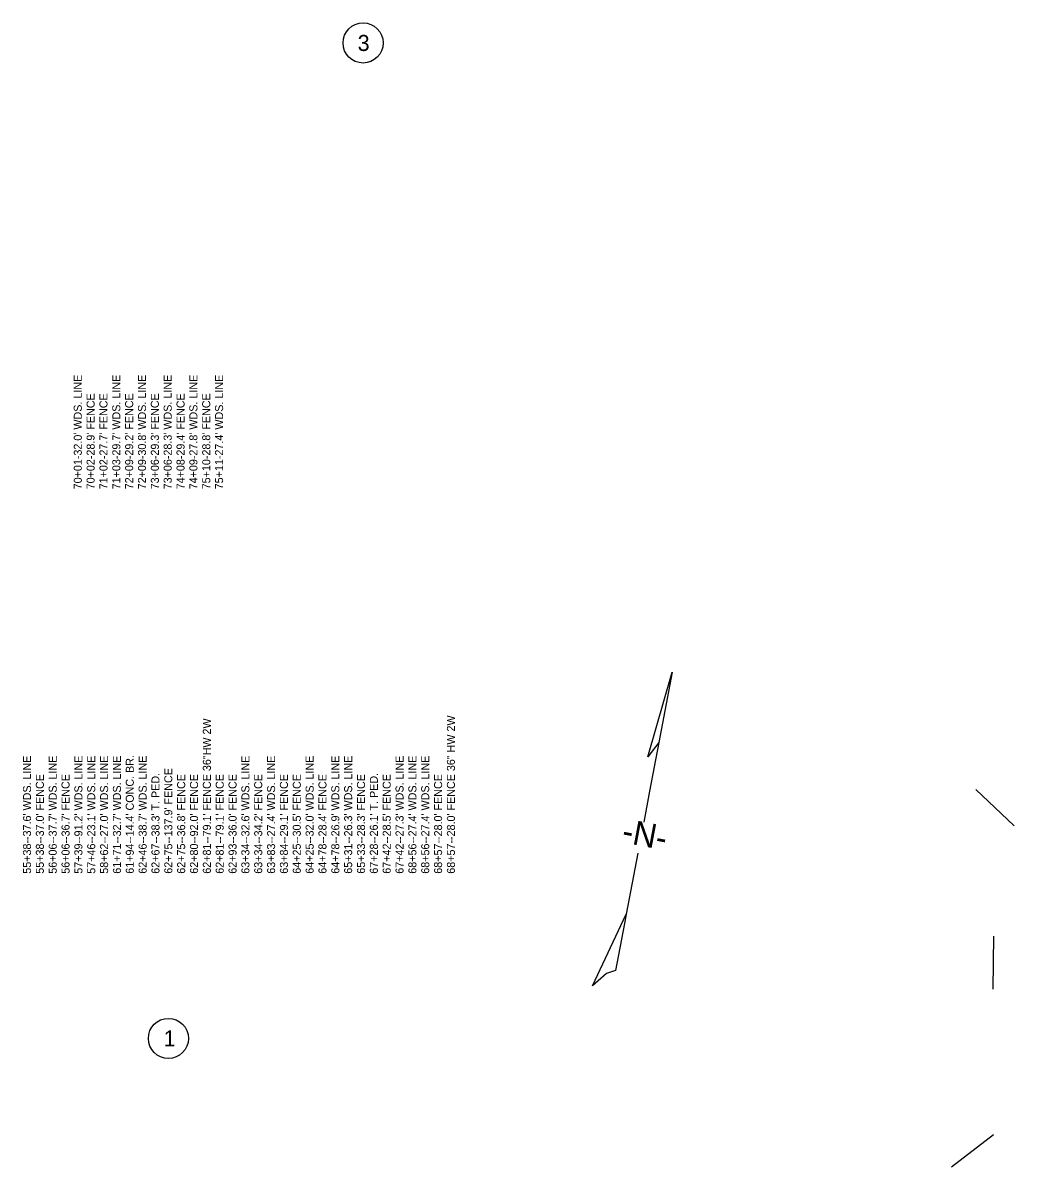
# Model space of a CAD drawing. Extents: x 1964853 to 1967410, y 1117103 to 1120421.
# Drawn here: x 1966020 to 1966637, y 1118961 to 1119674 of the extents above; entities that cross this region are included whole.
import ezdxf

# ---------------------------------------------------------------- set-up
doc = ezdxf.new("R2010")
doc.units = 0
for name, color, linetype in [('Level 10', 7, 'Continuous'), ('Level 12', 7, 'Continuous'), ('Level 2', 7, 'Continuous'), ('Level 24', 7, 'Continuous')]:
    doc.layers.add(name, color=color, linetype=linetype)

msp = doc.modelspace()

# ---------------------------------------------------------------- linework, layer by layer
at = {"layer": 'Level 10'}
for p, q in [((1966613.5, 1119196.31), (1966637.41, 1119173.56)), ((1966624.49, 1119104.85), (1966624.19, 1119071.85)), ((1966624.49, 1118981.29), (1966598.39, 1118961.09))]:
    msp.add_line(p, q, dxfattribs=at)
at = {"layer": 'Level 12'}
for centre in [(1966231.96, 1119661.16), (1966110.74, 1119041.23)]:
    msp.add_circle(centre, 12.5, dxfattribs=at)
at = {"layer": 'Level 2'}
for p, q in [((1966409.3, 1119216.53), (1966424.36, 1119269.24)), ((1966424.36, 1119269.24), (1966416.1, 1119225.56)), ((1966416.1, 1119225.56), (1966409.3, 1119216.53)), ((1966416.1, 1119225.56), (1966410.37, 1119195.28)), ((1966410.37, 1119195.28), (1966406.72, 1119175.97)), ((1966403.07, 1119156.7), (1966395.85, 1119118.53)), ((1966374.84, 1119074.05), (1966395.85, 1119118.53)), ((1966395.85, 1119118.53), (1966394.76, 1119112.75)), ((1966394.76, 1119112.75), (1966389.22, 1119083.49))]:
    msp.add_line(p, q, dxfattribs=at)
msp.add_lwpolyline([(1966389.22, 1119083.49), (1966383.46, 1119081.62), (1966374.84, 1119074.05)], dxfattribs=at)

# ---------------------------------------------------------------- texts
at = {"layer": 'Level 12'}
for s, p in [('3', (1966228.59, 1119656.16)), ('1', (1966107.7, 1119036.23))]:
    msp.add_text(s, height=10, dxfattribs=at).set_placement(p)
at = {"layer": 'Level 2'}
msp.add_text('-N-', height=15, rotation=349.28859, dxfattribs=at).set_placement((1966392.47, 1119163.5))
at = {"layer": 'Level 24'}
for s, p in [("70+01-32.0' WDS. LINE", (1966056.78, 1119383.19)), ("71+03-29.7' WDS. LINE", (1966080.78, 1119383.19)), ("72+09-30.8' WDS. LINE", (1966096.78, 1119383.19)), ("73+06-28.3' WDS. LINE", (1966112.78, 1119383.19)), ("74+09-27.8' WDS. LINE", (1966128.78, 1119383.19)), ("75+11-27.4' WDS. LINE", (1966144.78, 1119383.19)), ("70+02-28.9' FENCE  ", (1966064.78, 1119383.19)), ("71+02-27.7' FENCE  ", (1966072.78, 1119383.19)), ("72+09-29.2' FENCE  ", (1966088.78, 1119383.19)), ("73+06-29.3' FENCE  ", (1966104.78, 1119383.19)), ("74+08-29.4' FENCE  ", (1966120.78, 1119383.19)), ("75+10-28.8' FENCE  ", (1966136.78, 1119383.19)), ('62+81--79.1\' FENCE 36"HW 2W ', (1966137.17, 1119143.8)), ('68+57--28.0\' FENCE 36" HW 2W ', (1966289.17, 1119143.8)), ("55+38--37.6' WDS. LINE", (1966025.17, 1119143.8)), ("56+06--37.7' WDS. LINE", (1966041.17, 1119143.8)), ("57+39--91.2' WDS. LINE", (1966057.17, 1119143.8)), ("57+46--23.1' WDS. LINE", (1966065.17, 1119143.8)), ("58+62--27.0' WDS. LINE", (1966073.17, 1119143.8)), ("61+71--32.7' WDS. LINE", (1966081.17, 1119143.8)), ("61+94--14.4' CONC. BR.  ", (1966089.17, 1119143.8)), ("62+46--38.7' WDS. LINE", (1966097.17, 1119143.8)), ("63+34--32.6' WDS. LINE", (1966161.17, 1119143.8)), ("63+83--27.4' WDS. LINE", (1966177.17, 1119143.8)), ("64+25--32.0' WDS. LINE", (1966201.17, 1119143.8)), ("64+78--26.9' WDS. LINE", (1966217.17, 1119143.8)), ("65+31--26.3' WDS. LINE", (1966225.17, 1119143.8)), ("67+42--27.3' WDS. LINE", (1966257.17, 1119143.8)), ("68+56--27.4' WDS. LINE", (1966265.17, 1119143.8)), ("68+56--27.4' WDS. LINE", (1966273.17, 1119143.8)), ("62+75--137.9' FENCE  ", (1966113.17, 1119143.8)), ("55+38--37.0' FENCE  ", (1966033.17, 1119143.8)), ("56+06--36.7' FENCE  ", (1966049.17, 1119143.8)), ("62+67--38.3' T. PED.  ", (1966105.17, 1119143.8)), ("62+75--36.8' FENCE  ", (1966121.17, 1119143.8)), ("62+80--92.0' FENCE  ", (1966129.17, 1119143.8)), ("62+81--79.1' FENCE  ", (1966145.17, 1119143.8)), ("62+93--36.0' FENCE  ", (1966153.17, 1119143.8)), ("63+34--34.2' FENCE  ", (1966169.17, 1119143.8)), ("63+84--29.1' FENCE  ", (1966185.17, 1119143.8)), ("64+25--30.5' FENCE  ", (1966193.17, 1119143.8)), ("64+78--28.4' FENCE  ", (1966209.17, 1119143.8)), ("65+33--28.3' FENCE  ", (1966233.17, 1119143.8)), ("67+28--26.1' T. PED.  ", (1966241.17, 1119143.8)), ("67+42--28.5' FENCE  ", (1966249.17, 1119143.8)), ("68+57--28.0' FENCE  ", (1966281.17, 1119143.8))]:
    msp.add_text(s, height=5, rotation=90, dxfattribs=at).set_placement(p)

doc.saveas('drawing.dxf')
